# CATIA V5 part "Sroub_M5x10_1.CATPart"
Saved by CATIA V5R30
Part number: Sroub_M5x10_1
Definition: E 1220_5x10_2
Nomenclature: E 1220_5x10_2
Source: Unknown
Description: PART--DESC
Bounding box of the stored display mesh (mm): x 199 to 209, y 85.01 to 94.99, z -223.5 to -213.5
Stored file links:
  E:\Bakalarka\Model\Forma_v7\Sroub_M5x10_1.CATPart
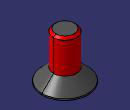
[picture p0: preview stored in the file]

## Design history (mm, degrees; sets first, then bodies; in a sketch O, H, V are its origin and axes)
Body1 "MANIFOLD_SOLID_BREP #4034" (main body)
  Solid1: solid without history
